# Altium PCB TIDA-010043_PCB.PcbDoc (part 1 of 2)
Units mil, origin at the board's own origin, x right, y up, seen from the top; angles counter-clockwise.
Board outline 2300 x 1555.91 mil, 4 copper layers (Top Layer, GND, PWR, Bottom Layer), stack 84.834 mil thick; 121 components, 65 nets, 295 pads, 120 vias.
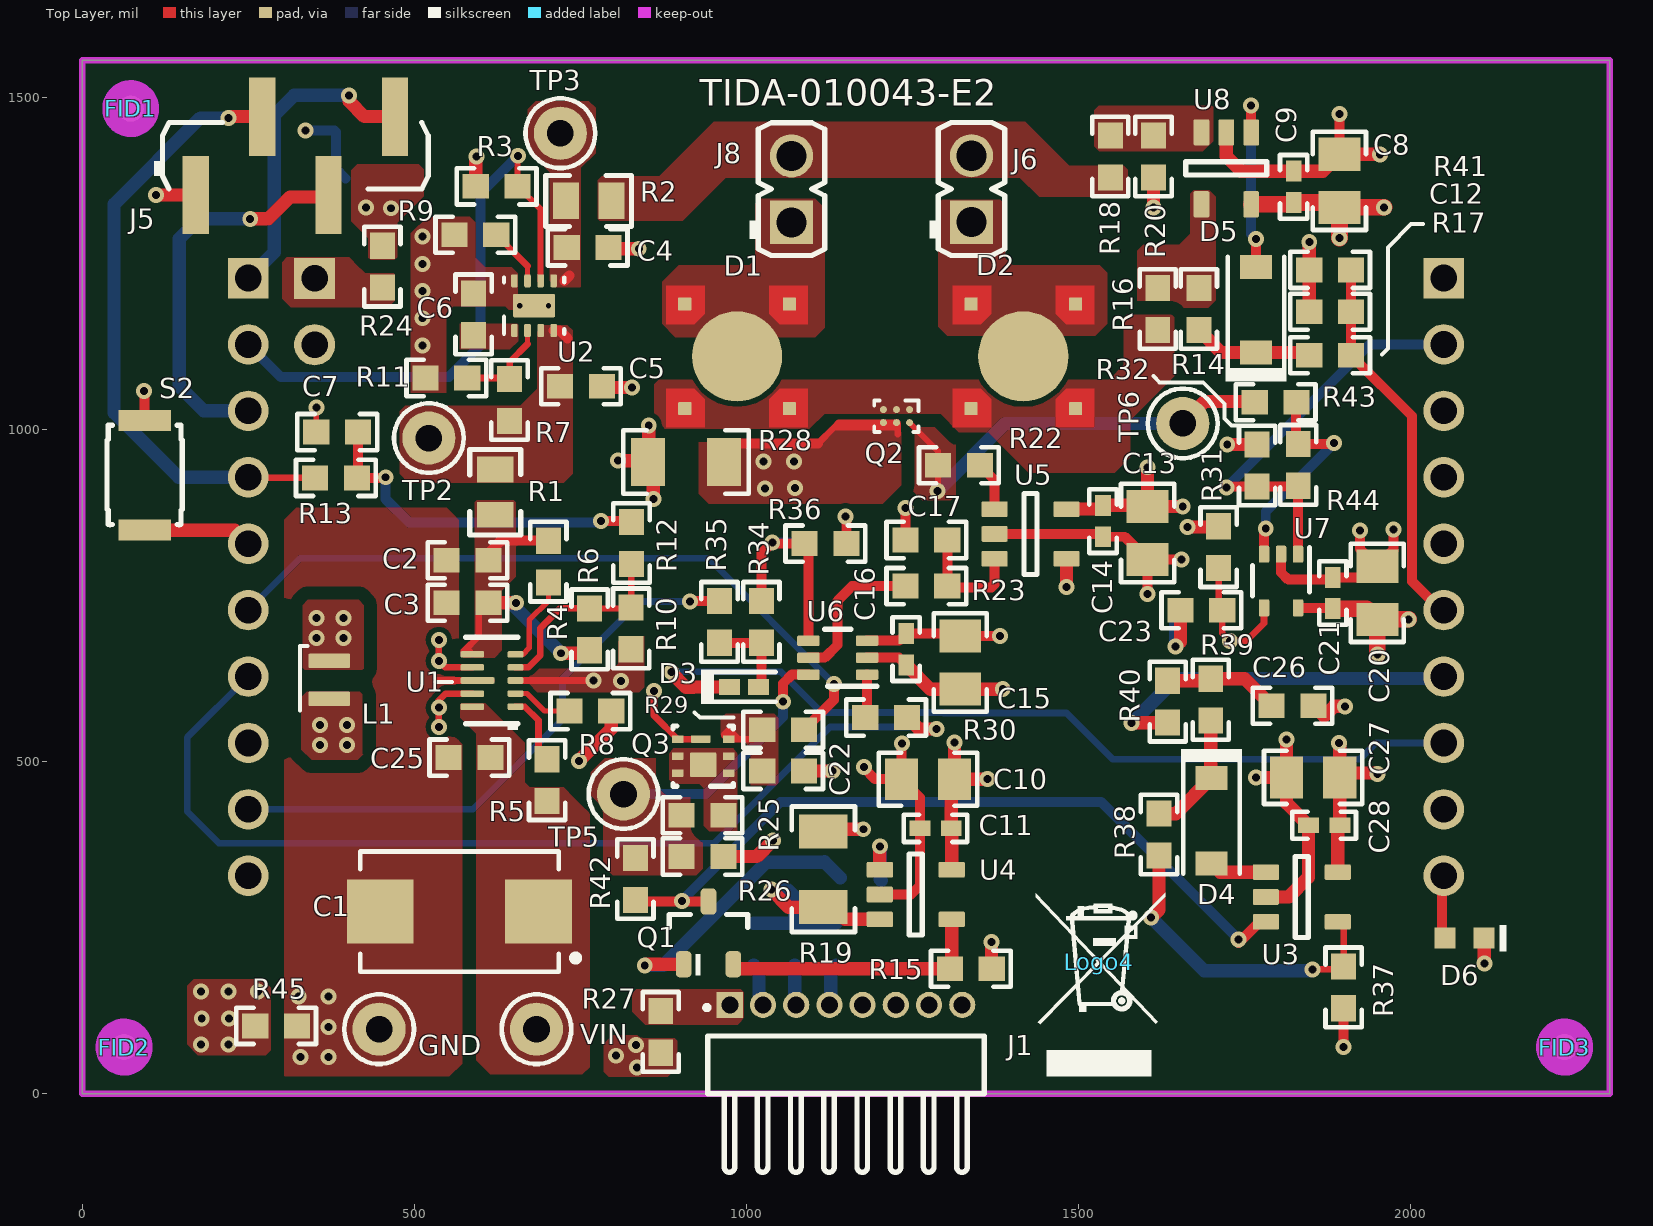
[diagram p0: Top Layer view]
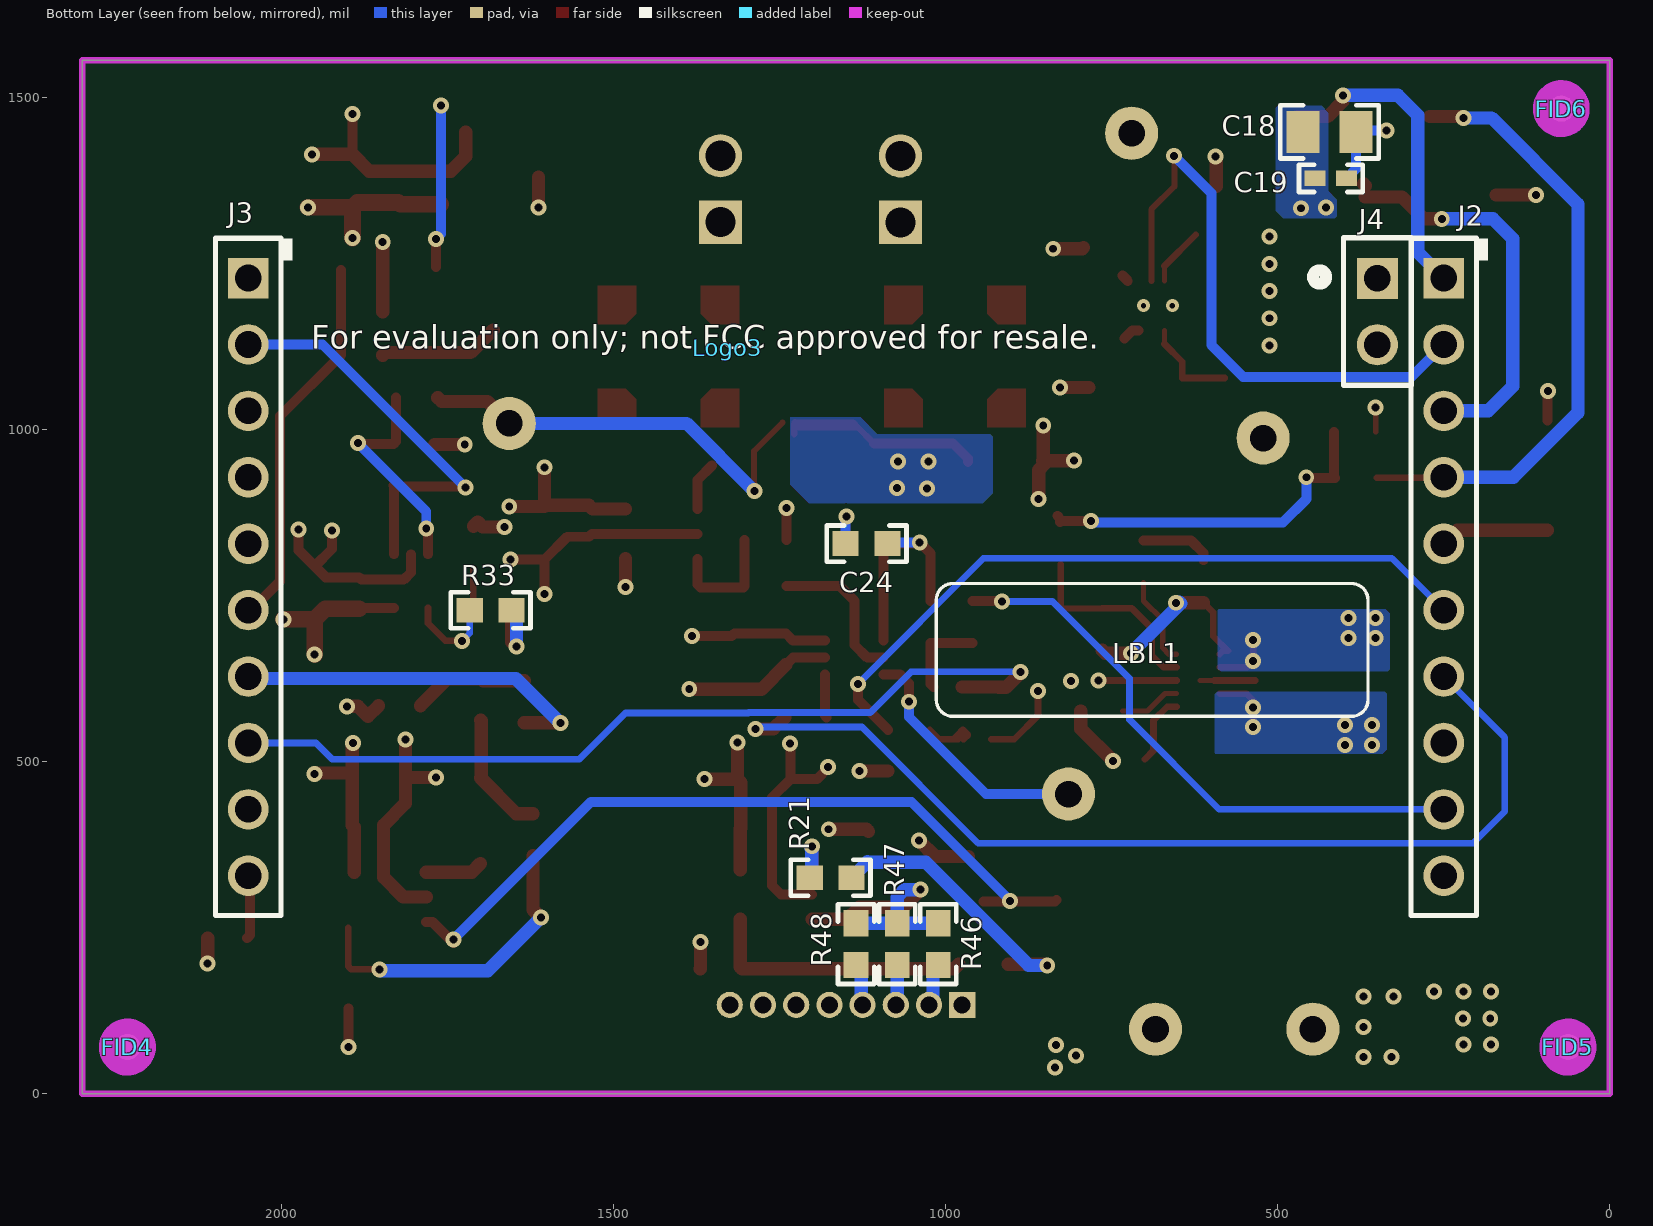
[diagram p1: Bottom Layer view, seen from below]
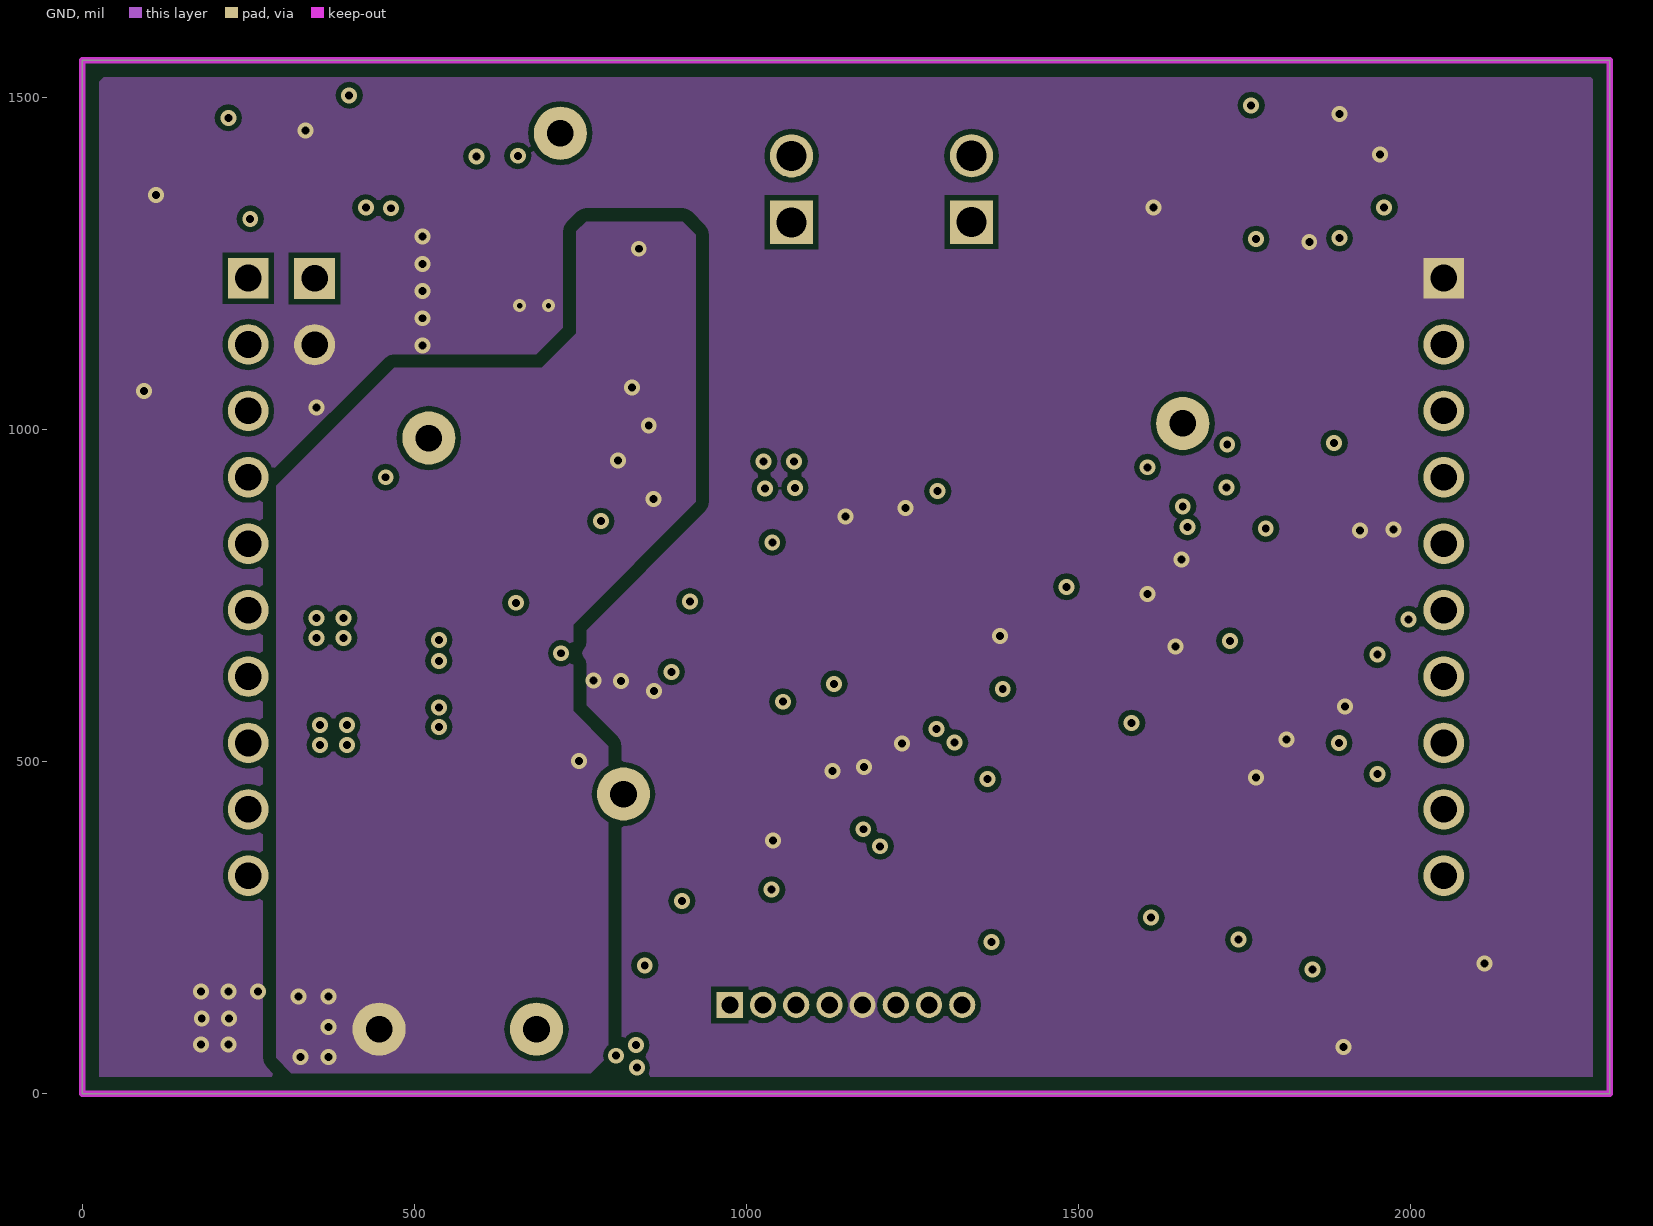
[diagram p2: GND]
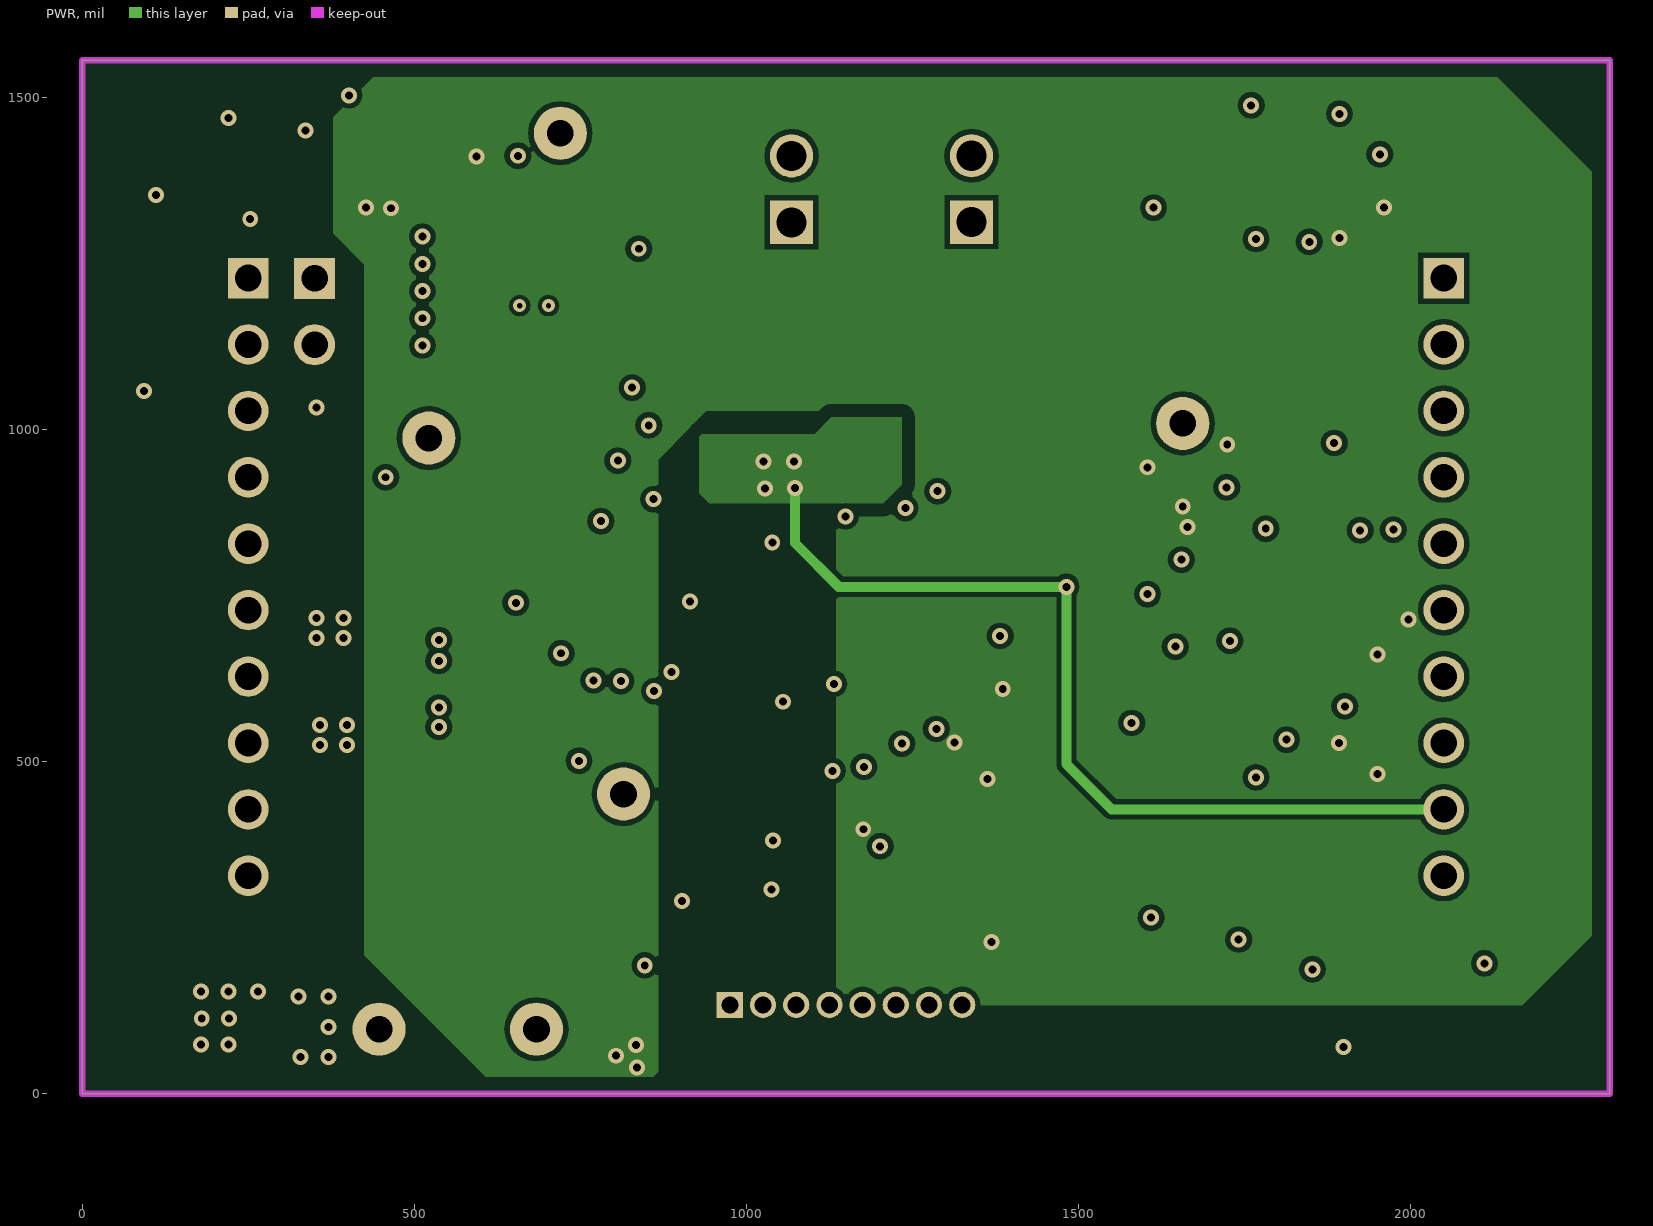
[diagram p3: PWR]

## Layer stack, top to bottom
Top Solder: solder mask 0.4, Solder Resist, Dk 3.5
Top Layer: signal copper 1.4
Dielectric 2: dielectric 10, FR-4 High Tg, Dk 4.2
GND: signal copper 1.417
Dielectric1: core 59.2, FR-4 High Tg, Dk 4.8
PWR: signal copper 1.417
Dielectric 3: dielectric 10, FR-4 High Tg, Dk 4.2
Bottom Layer: signal copper 1.4
Bottom Solder: solder mask 0.4, Solder Resist, Dk 3.5

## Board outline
0,0 2300,0 2300,1555.91 0,1555.91

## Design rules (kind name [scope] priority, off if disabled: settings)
AcuteAngle [All] p1: minimum=4.50000000000000E+0001 checktracksonly=FALSE
AssemblyTestPointUsage [All] p1: valid=2
BoardOutlineClearance BoardOutlineClearance_MountingHoles [OnCopper and InComponentClass('Mounting Holes')] p1: gap=0 ignorepadtopadclearanceinfootprint=FALSE
BoardOutlineClearance BoardOutlineClearance_Poly [OnCopper and IsPoly] p2: gap=0 ignorepadtopadclearanceinfootprint=FALSE
BoardOutlineClearance [OnCopper and Not InComponentClass('Logo') and not InComponentClass('FiducialMark') and not InRegion(1000,500,4000,800) and not InPoly] p3: gap=20 ignorepadtopadclearanceinfootprint=FALSE
Clearance "KEEPOU TO POLY" [IsKeepOut vs InPolygon] p1: gap=20 ignorepadtopadclearanceinfootprint=FALSE except(0: Arc-Hole Track-Hole SMDPad-Hole THPad-Hole Via-Hole Fill-Hole Poly-Hole Region-Hole Text-Hole)
Clearance U2 [InComponent('U2')] p2: gap=6 ignorepadtopadclearanceinfootprint=FALSE except(0: Arc-SMDPad Arc-Hole Track-Hole SMDPad-Hole THPad-Hole Via-Hole Fill-Hole Poly-Hole Region-Hole Text-Hole)
Clearance U1 [InComponent('U1')] p3: gap=6 ignorepadtopadclearanceinfootprint=FALSE except(0: Arc-SMDPad Arc-Hole Track-Hole SMDPad-Hole THPad-Hole Via-Hole Fill-Hole Poly-Hole Region-Hole Text-Hole)
Clearance Clearance_Poly [InPolygon vs InPolygon] p4: gap=20 ignorepadtopadclearanceinfootprint=FALSE except(0: Arc-SMDPad Arc-Hole Track-Hole SMDPad-Hole THPad-Hole Via-Hole Fill-Hole Poly-Hole Region-Hole Text-Hole)
Clearance [All] p5: gap=7.87 ignorepadtopadclearanceinfootprint=FALSE except(0: Arc-SMDPad Arc-Hole Track-Hole SMDPad-Hole THPad-Hole Via-Hole Fill-Hole Poly-Hole Region-Hole Text-Hole; 6: Arc-Arc Arc-Track Track-Track; 6.69: Track-SMDPad)
ComponentClearance ComponentClearance_MountingHoles_FiducialMarks [InComponentClass('Mounting Holes') vs InComponentClass('FiducialMark')] p1: gap=10 collisioncheckmode=3 verticalgap=10 showdistances=FALSE
ComponentClearance ComponentClearance_Shunt [InComponentClass('Header') vs InComponentClass('Shunt')] p2: gap=0 collisioncheckmode=3 verticalgap=0 showdistances=FALSE
ComponentClearance ComponentClearance_Logo [InComponentClass('Logo')] p3: gap=0 collisioncheckmode=3 verticalgap=0 showdistances=FALSE
ComponentClearance ComponentClearance_ScrewToNut [(HasFootprint('NY PMS 440 0025 PH')) vs (HasFootprint('Keystone_1902C'))] p4: gap=5 collisioncheckmode=3 verticalgap=10 showdistances=FALSE
ComponentClearance ComponentClearance_MountingHoles [InComponentClass('Mounting Holes')] p5: gap=10 collisioncheckmode=3 verticalgap=100000 showdistances=FALSE
ComponentClearance ComponentClearance_SmallPassives [HasFootprint('0201*') or HasFootprint('0402*') or HasFootprint('0508') or HasFootprint('0603*') or HasFootprint('0612') or HasFootprint('0805*') or HasFootprint('0815*') or HasFootprint('0830*') or HasFootprint('1206*') or HasFootprint('1210*') or HasFootprint('1808*') or HasFootprint('1812*') or HasFootprint('1825*') or HasFootprint('2010*') or HasFootprint('2220*') or HasFootprint('2225*') or HasFootprint('2512*') or HasFootprint('2728*') or HasFootprint('3518*') vs HasFootprint('0201*') or HasFootprint('0402*') or HasFootprint('0508') or HasFootprint('0603*') or HasFootprint('0612') or HasFootprint('0805*') or HasFootprint('0815*') or HasFootprint('0830*') or HasFootprint('1206*') or HasFootprint('1210*') or HasFootprint('1808*') or HasFootprint('1812*') or HasFootprint('1825*') or HasFootprint('2010*') or HasFootprint('2220*') or HasFootprint('2225*') or HasFootprint('2512*') or HasFootprint('2728*') or HasFootprint('3518*')] p6: gap=14.96 collisioncheckmode=3 verticalgap=10 showdistances=FALSE
ComponentClearance ComponentClearance_THtoSMT [IsThruComponent vs IsSMTComponent] p7: gap=0 collisioncheckmode=3 verticalgap=0 showdistances=FALSE
ComponentClearance ComponentClearance_THtoTH [IsThruComponent vs IsThruComponent] p8: gap=0 collisioncheckmode=3 verticalgap=0 showdistances=FALSE
ComponentClearance [All] p9: gap=0 collisioncheckmode=3 verticalgap=0 showdistances=FALSE
DiffPairsRouting [All] p1: maxlimit=100 minlimit=10 mostfreqgap=10 toplayer_minwidth=15 toplayer_maxwidth=15 toplayer_prefwidth=15 midlayer1_minwidth=15 midlayer1_maxwidth=15 midlayer1_prefwidth=15 midlayer2_minwidth=15 midlayer2_maxwidth=15 midlayer2_prefwidth=15 bottomlayer_minwidth=15 bottomlayer_maxwidth=15 bottomlayer_prefwidth=15 maxuncoupledlength=1000
FabricationTestPointUsage TestPointUsage [All] p1: valid=2 allowmultiple=FALSE
FabricationTestpoint Testpoint [All] p1: side=3 testpointundercomponent=TRUE minsize=40 maxsize=100 preferedsize=60 minholesize=0 maxholesize=40 preferedholesize=32 testpointgrid=1 allowsidetop=TRUE allowsidebottom=TRUE usegrid=TRUE gridtolerance=0.01
FanoutControl Fanout_LCC [IsLCC] p1: bgadir=Out bgaviamode=Centered fanoutstyle=Auto fanoutdirection=Alternating viagrid=1 // Fanout_LCC (Default Rule)
FanoutControl Fanout_BGA [IsBGA] p2: bgadir=Out bgaviamode=Centered fanoutstyle=Auto fanoutdirection=Alternating viagrid=1 // Fanout_BGA (Default Rule)
FanoutControl Fanout_Default [All] p4: bgadir=Out bgaviamode=Centered fanoutstyle=Auto fanoutdirection=Alternating viagrid=1 // Fanout_Default (Default Rule)
FanoutControl Fanout_Small [(CompPinCount < 5)] p5: bgadir=Out bgaviamode=Centered fanoutstyle=Auto fanoutdirection=OutThenIn viagrid=1 // Fanout_Small (Default Rule)
HoleSize [All] p1: absolutevalues=TRUE maxlimit=251 minlimit=7.87 maxpercent=80.000 minpercent=20.000
MinimumAnnularRing MinimumAnnularRing_ThermalPadVias [IsVia and InAnyComponent] p1: minimumring=5.91
MinimumAnnularRing [All] p2: minimumring=6
MinimumSolderMaskSliver MinimumSolderMaskSliver_Logo [InComponentClass('Logo') vs InComponentClass('Logo')] p1: minsoldermaskwidth=0.7
MinimumSolderMaskSliver [All] p2: minsoldermaskwidth=3.94
PlaneConnect [All] p1: planeconnectstyle=Direct reliefexpansion=10 reliefentries=4 reliefconductorwidth=10 reliefairgap=10
PolygonConnect [All] p1: connectstyle=Direct reliefconductorwidth=10 reliefentries=4 polygonreliefangle="90 Angle" airgapwidth=10
RoutingVias ThermalPadVias [IsVia and InAnyComponent] p1: holewidth=7.87 width=19.68 viastyle="Through Hole" minholewidth=7.87 minwidth=19.68 maxholewidth=12.99 maxwidth=23.62
RoutingVias [All] p2: holewidth=12 width=24 viastyle="Through Hole" minholewidth=12 minwidth=24 maxholewidth=12 maxwidth=24
SilkToBoardRegionClearance [Not ((IsComment or IsDesignator) And (Hide <> 'False')) and not InRegion(1000,500,4000,800)] p1:
SilkToSilkClearance SilkToSilkClearance_Pb-FreeLogo [(HasFootprint('Pb-Free_Overlay_Medium') OR HasFootprint('Pb-Free_Overlay_Small')) vs (HasFootprint('Pb-Free_Overlay_Medium') OR HasFootprint('Pb-Free_Overlay_Small'))] p1: silktosilkclearance=0
SilkToSilkClearance [All] p2: silktosilkclearance=4
SilkToSolderMaskClearance SilkToComponentPadClearance [(IsPad or IsFill or IsRegion) and InAnycomponent] p1: minsilkscreentomaskgap=5 clearancetoexposedcopper=TRUE
SilkToSolderMaskClearance "Silk to Solder Mask Opening" [All] p2: minsilkscreentomaskgap=4 clearancetoexposedcopper=FALSE
SolderMaskExpansion [All] p1: expansion=1.97
Width [All] p1: maxlimit=100 minlimit=8 preferedwidth=15 checkconnectedcopper=TRUE
15 further rules are at their usual default settings.

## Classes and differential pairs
component class TIDA-010043_Main: C1 C2 C3 C4 C5 C6 C7 C8 C9 C10 C11 C12 C13 C14 C15 C16 C17 C18 C19 C20 C21 C22 C23 C24 C25 C26 C27 C28 D1 D2 D3 D4 D5 D6 GND J1 J2 J3 J4 J5 J6 J8 L1 Q1 Q2 Q3 R1 R2 R3 R4 R5 R6 R7 R8 R9 R10 R11 R12 R13 R14 R15 R16 R17 R18 R19 R20 R21 R22 R23 R24 R25 R26 R27 R28 R29 R30 R31 R32 R33 R34 R35 R36 R37 R38 R39 R40 R41 R42 R43 R44 R45 R46 R47 R48 S2 TP2 TP3 TP5 TP6 U1 U2 U3 U4 U5 U6 U7 U8 VIN
component class TIDA-010043_EVM_Hardware: FID1 FID2 FID3 FID4 FID5 FID6 LBL1 Logo3 Logo4 ZZ1 ZZ2 ZZ3 ZZ4
component class FiducialMark: FID1 FID2 FID3 FID4 FID5 FID6
component class AssemblyNote: ZZ1 ZZ2 ZZ3 ZZ4
component class Label: LBL1
component class Header: J5 J6 J8

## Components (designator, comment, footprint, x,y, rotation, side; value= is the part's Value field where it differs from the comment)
C1 "T495D686K020ATE150" 7343-31 568,274 r180 top value=68uF
C2 "GRM188R60J226MEA0D" 0603 580.13,803 r180 top value=22uF
C3 "GRM188R60J226MEA0D" 0603 580.13,739 r180 top value=22uF
C4 "GRM188Z71A106MA73D" 0603 761,1274 r0 top value=10uF
C5 "06033C104KAT2A" 0603 751,1065 r0 top value=0.1uF
C6 "GRM188R71E332KA01D" 0603 589.32,1173.37 r90 top value=3300pF
C7 "06033C104KAT2A" 0603 384,996 r180 top value=0.1uF
C8 "885012207026" 0805_HV 1893,1374.22 r90 top value=10uF
C9 "885012205037" 0402 1824,1365.22 r90 top value=0.1uF
C10 "885012207026" 0805_HV 1273.43,473.37 r180 top value=10uF
C11 "885012205037" 0402 1284.81,399.37 r180 top value=0.1uF
C12 "06033C104KAT2A" 0603 1879,1177.22 r180 top value=0.1uF
C13 "885012207026" 0805_HV 1604,844 r270 top value=10uF
C14 "885012205037" 0402 1537,862 r270 top value=0.1uF
C15 "885012207026" 0805_HV 1322,649 r90 top value=10uF
C16 "885012205037" 0402 1240.56,669.21 r90 top value=0.1uF
C17 "06033C104KAT2A" 0603 1271,833.53 r180 top value=0.1uF
C18 "885012207026" 0805_HV 422,1448 r180 bottom value=10uF
C19 "885012205037" 0402 420,1378 r180 bottom value=0.1uF
C20 "885012207026" 0805_HV 1950,754 r90 top value=10uF
C21 "885012205037" 0402 1883,753.71 r90 top value=0.1uF
C22 "06033C104KAT2A" 0603 1055.35,485.7 r0 top value=0.1uF
C23 "06033C104KAT2A" 0603 1685,727.71 r180 top value=0.1uF
C24 "06033C104KAT2A" 0603 1119,828.21 r0 bottom value=0.1uF
C25 "GRM188R60J106ME84" 0603 583,506 r180 top value=10uF
C26 "GRM188R71A474KA61D" 0603 1822.29,584 r0 top value=0.47uF
C27 "885012207026" 0805_HV 1853.29,476 r180 top value=10uF
C28 "885012205037" 0402 1869.91,404 r180 top value=0.1uF
D1 "LZ1-00G102-0000" LED_LZ1_Green 986,1110 r270 top value=Green
D2 "LZ1-00R102-0000" LED_LZ1_Red 1417,1109.92 r90 top value=Red
D3 "ZLLS350TA" SOD-523 996.56,612.21 r0 top value=40V
D4 "1N4148W-7-F" SOD-123 1700.29,411 r270 top value=100V
D5 "1N4148W-7-F" SOD-123 1767.32,1180.22 r90 top value=100V
D6 "SM0603GCL" SM0603GCL_GREEN 2081.29,234 r0 top value=Green
FID1 "Fiducial" Fiducial10-20 73,1483 r0 top
FID2 "Fiducial" Fiducial10-20 63,70 r0 top
FID3 "Fiducial" Fiducial10-20 2232,70 r0 top
FID4 "Fiducial" Fiducial10-20 2232,70 r180 bottom
FID5 "Fiducial" Fiducial10-20 63,70 r180 bottom
FID6 "Fiducial" Fiducial10-20 73,1483 r180 bottom
GND "5001" Keystone5001 447,97 r90 top
J1 "850-10-008-20-001000" Mill-Max_850-10-008-20-001000 1150,0 r0 top
J2 "61301011821" Wurth_61301011821 250,777.95 r270 bottom
J3 "61301011821" Wurth_61301011821 2050,777.95 r270 bottom
J4 "PPTC021LFBN-RC" CONN_PPTC021LFBN-RC 350,1177.46 r90 bottom
J5 "61000418221" Wurth_61000418221 321,1412 r90 top
J6 "61300211121" WURTH_61300211121 1339,1362 r90 top
J8 "61300211121" WURTH_61300211121 1068,1361.86 r90 top
L1 "DFE201612E-R47M=P2" DFE201612E 372,623 r90 top value=470nH
LBL1 "Size: 0.65\" x 0.20 \"" Label_650x200 689,668 r180 bottom
Logo3 "FCC disclaimer" FCC_disclaimer 1328,1123 r180 bottom
Logo4 "WEEE logo" WEEE_Minimum 1531,198 r0 top
Q1 "BC857C-7-F" SOT-23 943,242 r90 top value="45 V"
Q2 "CSD13306W" YZC0006ABAB 1226,1020 r270 top value=12V
Q3 "CSD13202Q2" DQK0006C 935,508 r180 top value=12V
R1 "5106" 5106 622,905 r90 top value=0
R2 "5106" 5106 762,1344 r0 top value=0
R3 "RC0603FR-0710K2L" 0603 624,1366 r180 top value=10.2k
R4 "RC0603FR-07806KL" 0603 764,699 r270 top value=806k
R5 "RMCF0603ZT0R00" 0603 700,472 r90 top value=0
R6 "CRCW0603100KFKEA" 0603 702,800.94 r270 top value=100k
R7 "RC0603FR-071ML" 0603 643.32,1044.37 r270 top value=1.00Meg
R8 "RMCF0603ZT0R00" 0603 765,576 r180 top value=0
R9 "RC0603FR-071K4L" 0603 592,1293 r0 top value=1.40k
R10 "CRCW0603100KFKEA" 0603 826.5,700.45 r270 top value=100k
R11 "RC0603FR-07390KL" 0603 548.32,1077.37 r0 top value=390k
R12 "RC0603FR-07806KL" 0603 827,829 r270 top value=806k
R13 "RMCF0603ZT0R00" 0603 382,927 r180 top value=0
R14 "RMCF0603FT10K0" 0603 1681.32,1181.22 r270 top value=10.0k
R15 "ERJ-3EKF1001V" 0603 1338,188 r0 top value=1.00k
R16 "RMCF0603FT10K0" 0603 1619.32,1181.22 r90 top value=10.0k
R17 "RMCF0603ZT0R00" 0603 1879,1111.68 r0 top value=0
R18 "RMCF0603FT10K0" 0603 1548,1411 r90 top value=10.0k
R19 "CRCW120620R0FKEAHP" 1206 1116,337.68 r90 top value=20.0
R20 "RMCF0603FT10K0" 0603 1613,1411 r90 top value=10.0k
R21 "RMCF0603ZT0R00" 0603 1173,325.05 r180 bottom value=0
R22 "RMCF0603ZT0R00" 0603 1320,946 r180 top value=0
R23 "RMCF0603ZT0R00" 0603 1271,764 r0 top value=0
R24 "RMCF0603ZT0R00" 0603 452,1245 r90 top value=0
R25 "CRCW06032R49FKEA" 0603 934,419 r180 top value=2.49
R26 "CRCW060349R9FKEA" 0603 934,357 r180 top value=49.9
R27 "RMCF0603ZT0R00" 0603 871,93 r270 top value=0
R28 "CRM1206-FZ-R050ELF" 1206 909,951 r0 top value=0.05
R29 "RMCF0603ZT0R00" 0603 1055.35,547.7 r180 top value=0
R30 "RMCF0603ZT0R00" 0603 1210.56,566.21 r180 top value=0
R31 "RC0603FR-0710K2L" 0603 1711,822.71 r90 top value=10.2k
R32 "RC0603FR-0710K2L" 0603 1769,945.71 r90 top value=10.2k
R33 "RC0603FR-0710K2L" 0603 1685,727.71 r0 bottom value=10.2k
R34 "RMCF0603ZT0R00" 0603 1022.56,710.21 r270 top value=0
R35 "RMCF0603ZT0R00" 0603 959.56,710.21 r90 top value=0
R36 "RMCF0603ZT0R00" 0603 1119,828.21 r180 top value=0
R37 "RC0603FR-071ML" 0603 1899.29,160 r90 top value=1.00Meg
R38 "RC0603FR-072ML" 0603 1621.29,390 r90 top value=2.00Meg
R39 "RMCF0603ZT0R00" 0603 1699.29,593 r90 top value=0
R40 "RMCF0603ZT0R00" 0603 1634.29,590 r270 top value=0
R41 "RC0603FR-07100KL" 0603 1879,1240.22 r0 top value=100k
R42 "ERJ-3EKF1001V" 0603 833,323 r270 top value=1.00k
R43 "ERJ-3EKF2202V" 0603 1797,1041 r0 top value=22.0k
R44 "RC0603FR-07470KL" 0603 1831,946.71 r270 top value=470k
R45 "RMCF0603ZT0R00" 0603 292,102 r180 top value=0
R46 "RMCF0603ZT0R00" 0603 1011,225 r90 bottom value=0
R47 "RMCF0603ZT0R00" 0603 1072.94,225 r90 bottom value=0
R48 "RMCF0603ZT0R00" 0603 1134.87,225 r90 bottom value=0
S2 "SKRKAEE010" SW_SKRKAEE010 94,931 r90 top
TP2 "5000" Keystone5000 521.98,987 r90 top
TP3 "5000" Keystone5000 720,1446 r90 top
TP5 "5000" Keystone5000 815,451 r0 top
TP6 "5000" Keystone5000 1657,1009 r90 top
U1 "TPS63802DLAR" DLA0010A 616.92,621.95 r180 top
U2 "TPS259571DSGR" DSG0008A 680.32,1186.37 r90 top
U3 "OPA333AIDBVR" DBV0005A_N 1836.29,296 r0 top
U4 "OPA365AIDBVR" DBV0005A_N 1255,299.68 r0 top
U5 "OPA365AIDBVR" DBV0005A_N 1427.84,842.62 r0 top
U6 "TS5A9411DCKR" DCK0006A_N 1137.56,656.26 r180 top
U7 "TLV7021DCKR" DCK0005A_L 1805,771.71 r270 top
U8 "OPA333AIDBVR" DBV0005A_N 1722.6,1393.08 r270 top
VIN "5000" Keystone5000 684,97 r90 top
ZZ1 "This Assembly Note is for PCB labels only" AssemblyNoteLabel 181.5,3681.95 r0 top
ZZ2 "These assemblies are ESD sensitive, ESD precautions shall be observed." AssemblyNote 185,3607.07 r0 top
ZZ3 "These assemblies must be clean and free from flux and all contaminants. Use of no clean flux is not acceptable." AssemblyNote 185,3518.51 r0 top
ZZ4 "These assemblies must comply with workmanship standards IPC-A-610 Class 2, unless otherwise specified." AssemblyNote 185,3429.95 r0 top

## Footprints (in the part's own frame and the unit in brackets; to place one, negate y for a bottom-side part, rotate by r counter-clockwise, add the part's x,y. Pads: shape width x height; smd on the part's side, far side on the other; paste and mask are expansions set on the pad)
0402 [mm] "0402 from SM-752 data"
  rect 0.8x0.6 smd: 1(-0.6,0) 2(0.6,0)
  silkscreen extent -1.22,-0.52 1.22,0.52, body extent -0.55,-0.3 0.55,0.3, height 0.6
0603 [mm] "0603 from SM-752 data"
  rect 1x0.95 smd: 1(-0.8,0) 2(0.8,0)
  silkscreen extent -1.52,-0.69 1.52,0.69, body extent -0.87,-0.47 0.87,0.47, height 1
0805_HV [mil] "0805 with 30mil clearance between pads"
  rect 50x63 smd: 1(-40,0) 2(40,0)
  silkscreen extent -74,-40 74,40, body extent -43,-29 43,29, height 57
1206 [mm] "1206 from SM-752 data"
  rect 1.3x1.85 smd: 1(-1.45,0) 2(1.45,0)
  silkscreen extent -2.4,-1.21 2.4,1.21, body extent -1.7,-0.9 1.7,0.9, height 1.35
5106 [mm] "Keystone"
  rect 0.99x1.4 smd: 1(-0.85,0) 2(0.88,0)
  silkscreen extent -1.63,-0.97 1.65,0.97, body extent -1.06,-0.69 1.06,0.69, height 0.84
7343-31 [mm] "Medium Density based on Kemet T495 dimensions"
  rect 2.55x2.45 smd: 1(-3.025,0) 2(3.025,0)
  silkscreen extent -4.56,-2.3 3.8,2.3, body extent -3.8,-2.3 3.8,2.3, height 3.1
AssemblyNote [mil] "Assembly Note"
AssemblyNoteLabel [mil] "Assembly Note for PCB Labels"
CONN_PPTC021LFBN-RC [mil] "SULLINS"
  rect 62x62 hole 40: 1(50,0)
  round 62 hole 40.16: 2(-50,0)
  silkscreen extent -111,-51 111,97, body extent -110,-50 110,50, height 336
DBV0005A_N [mm] "SOT23, 5-Leads, Body 2.9x1.6mm, Pitch 0.95mm, Lead Span 2.8mm, IPC Medium Density"
  rrect17% 1x0.6 smd: 1(-1.375,0.95) 2(-1.375,0) 3(-1.375,-0.95) 4(1.375,-0.95) 5(1.375,0.95)
  silkscreen extent -0.25,-1.55 0.25,1.55, body extent -1.42,-1.46 1.42,1.46, height 1.09
DCK0005A_L [mm] "SOT353, 5-Leads, Body 2x1.3mm, Pitch 0.65mm, Lead Span 2.1mm, IPC High Density"
  rrect25% 0.65x0.4 smd: 1(-1.025,0.65) 2(-1.025,0) 3(-1.025,-0.65) 4(1.025,-0.65) 5(1.025,0.65)
  silkscreen extent -1.27,-1.09 0.56,1.09, body extent -1.14,-1 1.14,1, height 0.95
DCK0006A_N [mm] "SOT23, 6-Leads, Body 2x1.3mm, Pitch 0.65mm, Lead Span 2.1mm, IPC Medium Density"
  rrect25% 0.85x0.4 smd: 1(-1.125,0.65) 2(-1.125,0) 3(-1.125,-0.65) 4(1.125,-0.65) 5(1.125,0) 6(1.125,0.65)
  silkscreen extent -1.5,-1.09 0.51,1.09, body extent -1.14,-1 1.14,1, height 0.95
DFE201612E [mm] "MuRata recommended"
  rrect18% 0.55x1.6 smd: 1(-0.725,0) 2(0.725,0)
  body extent -1.1,-0.9 1.1,0.9, height 1.2
DLA0010A [mm] "VQFN-HR-10"
  rrect40% 0.6x0.25 smd: 1(-0.9,1) 2(-0.9,0.5) 3(-0.9,0) 4(-0.9,-0.5) 5(-0.9,-1)
  rrect40% 0.9x0.25 smd: 6(0.75,-1) 7(0.75,-0.5) 9(0.75,0.5) 10(0.75,1)
  rrect40% 1.3x0.25 smd paste-1: 8(0.55,0)
  silkscreen extent -1,-1.65 1,1.9, body extent -1,-1.5 1,1.5, height 1
DQK0006C [mm] "WSON"
  rrect12% 0.9x0.86 on Top Paste: 0(0,0.325)
  rrect34% 0.7x0.29 on Top Paste: 0(0.095,-0.65)
  rrect33% 0.45x0.3 smd: 1(-0.975,0.65) 2(-0.975,0) 3(-0.975,-0.65) 4(0.975,-0.65) 5(0.975,0) 6(0.975,0.65)
  rrect33% 0.75x0.3 smd paste-0.15: 7(0.095,-0.65)
  rrect11% 1x0.95 smd paste-0.5: 8(0,0.325)
  silkscreen extent -1.15,-1.15 1.15,1.15, body extent -1,-1 1,1, height 0.82
DSG0008A [mm] "SON, 8-Leads, Body 2x2mm, Pitch 0.5mm, Thermal Pad 1.6x0.9mm, TI Recommended"
  rrect40% 0.5x0.25 smd: 1(-0.95,0.75) 2(-0.95,0.25) 3(-0.95,-0.25) 4(-0.95,-0.75) 5(0.95,-0.75) 6(0.95,-0.25) 7(0.95,0.25) 8(0.95,0.75)
  rrect14% 0.9x0.7 on Top Paste: 9(0,0.45) 9(0,-0.45)
  rrect11% 0.9x1.6 smd paste-0.45: 9(0,0)
  silkscreen extent -1.07,-1.15 1.07,1.15, body extent -1,-1 1,1, height 0.77
FCC_disclaimer [mil]
Fiducial10-20 [mm]
  round 1 smd mask+0.5: 1(0,0)
  Top Layer keep-out circle w1.178: c0,0 r0.5
Keystone5000 [mil] "For Keystone 500x miniature loop terminals"
  round 80 hole 40: 1(0,0)
  silkscreen extent -52,-52 52,52, body extent -49,-49 49,49, height 182
Keystone5001 [mil] "For Keystone 500x miniature loop terminals"
  round 80 hole 40: 1(0,0)
  silkscreen extent -52,-52 52,52, body extent -49,-49 49,49, height 182
Label_650x200 [mil] "Thermal Transfer Label"
  silkscreen extent -325,-100 325,100, body extent -325,-100 325,100, height 1
LED_LZ1_Green [mm] "SMD, 5-Leads, Body 4.4x4.4m"
  rrect12% 0.5x0.5 smd: 1(-2,2) 2(2,2) 3(2,-2) 4(-2,-2)
  round 3.45 smd paste-0.125 mask-0.125: 5(0,0)
  Top Layer region: 2.706,2.704 2.706,1.234 1.636,1.234 1.236,1.634 1.236,2.704
  Top Layer region: 2.706,-2.706 1.236,-2.706 1.236,-1.636 1.636,-1.236 2.706,-1.236
  Top Layer region: -2.704,2.704 -1.234,2.704 -1.234,1.634 -1.634,1.234 -2.704,1.234
  Top Layer region: -2.704,-2.706 -2.704,-1.236 -1.634,-1.236 -1.234,-1.636 -1.234,-2.706
  body extent -2.2,-2.2 2.2,2.2, height 2.35
LED_LZ1_Red [mm] "SMD, 5-Leads, Body 4.4x4.4m"
  rrect12% 0.5x0.5 smd: 1(-2,2) 2(2,2) 3(2,-2) 4(-2,-2)
  round 3.45 smd paste-0.125 mask-0.125: 5(0,0)
  Top Layer region: 2.706,2.704 2.706,1.234 1.636,1.234 1.236,1.634 1.236,2.704
  Top Layer region: 2.706,-2.706 1.236,-2.706 1.236,-1.636 1.636,-1.236 2.706,-1.236
  Top Layer region: -2.704,2.704 -1.234,2.704 -1.234,1.634 -1.634,1.234 -2.704,1.234
  Top Layer region: -2.704,-2.706 -2.704,-1.236 -1.634,-1.236 -1.234,-1.636 -1.234,-2.706
  body extent -2.2,-2.2 2.2,2.2, height 2.35
Mill-Max_850-10-008-20-001000 [mm] "Mill-Max"
  rect 1x1 hole 0.65: 1(-4.445,3.394)
  round 1 hole 0.65: 2(-3.175,3.394) 3(-1.905,3.394) 4(-0.635,3.394) 5(0.635,3.394) 6(1.905,3.394) 7(3.175,3.394) 8(4.445,3.394)
  silkscreen extent -5.37,-3.01 5.28,3.34, body extent -5.27,-3 5.27,3.6, height 2.21
SM0603GCL_GREEN [mm] "BIVAR"
  rect 0.8x0.8 smd: 1(-0.75,0) 2(0.75,0)
  silkscreen extent 1.35,-0.51 1.6,0.51, body extent -0.93,-0.52 0.93,0.52, height 0.86
SOD-123 [mm] "On Semi recommended land pattern"
  rect 0.915x1.22 smd: 1(-1.637,0) 2(1.637,0)
  silkscreen extent -2.74,-1.17 2.03,1.17, body extent -1.93,-0.9 1.93,0.9, height 1.35
SOD-523 [mm] "NXP Semiconductor recommended land pattern, nominal STEP model"
  rect 0.8x0.6 smd paste-0.05: 1(-0.55,0) 2(0.55,0)
  silkscreen extent -1.65,-0.66 1.2,0.66, body extent -0.8,-0.4 0.8,0.4, height 0.72
SOT-23 [mm] "SOT23, 3-Leads, Body 2.9x1.3mm, Pitch 0.95mm, Lead Span 2.5mm, IPC Medium Density"
  rrect50% 1x0.6 smd: 1(-1.2,0.95) 2(-1.2,-0.95) 3(1.2,0)
  silkscreen extent -1.62,-1.5 0.7,1.5, body extent -1.16,-1.45 1.21,1.45, height 1
SW_SKRKAEE010 [mm] "Alps recommended land pattern"
  rect 0.8x2 smd: 1(-2.1,0) 2(2.1,0)
  silkscreen extent -1.9,-1.44 1.92,1.44, body extent -2.4,-1.45 2.4,1.45, height 1.96
WEEE_Minimum [mil] "WEEElie bin"
  silkscreen extent -95,-172 99,104
Wurth_61000418221 [mm] "Header, 2.54mm, 4x1, SMT"
  rect 3x1 smd: 1(-1.5,3.81) 2(1.5,1.27) 3(-1.5,-1.27) 4(1.5,-3.81)
  silkscreen extent -1.27,-5.08 1.27,5.4, body extent -2.5,-5.08 2.5,5.08, height 9.29
WURTH_61300211121 [mm] "Header, 2.54mm, 2x1, TH"
  rect 1.65x1.65 hole 1.15: 1(-1.27,0)
  round 1.65 hole 1.15: 2(1.27,0)
  silkscreen extent -2.54,-1.27 2.54,1.6, body extent -2.54,-1.27 2.54,1.27, height 8.54
Wurth_61301011821 [mm] "Receptacle, 2.54mm, 10x1, TH"
  rect 1.55x1.55 hole 1.02: 1(-11.43,0)
  round 1.55 hole 1.02: 2(-8.89,0) 3(-6.35,0) 4(-3.81,0) 5(-1.27,0) 6(1.27,0) 7(3.81,0) 8(6.35,0) 9(8.89,0) 10(11.43,0)
  silkscreen extent -12.95,-1.25 12.95,1.7, body extent -12.95,-1.25 12.95,1.25, height 8.5
YZC0006ABAB [mm] "DSBGA"
  round 0.265 smd paste-0.125: A1(-0.25,0.5) A2(0.25,0.5) B1(-0.25,0) B2(0.25,0) C1(-0.25,-0.5) C2(0.25,-0.5)
  silkscreen extent -0.6,-0.85 0.6,0.85, body extent -0.5,-0.75 0.5,0.75, height 0.63

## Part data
C1: library part CMP-0011790-2, "CAP, TA, 68 uF, 20 V, +/- 10%, 0.15 ohm, SMD", Cap_Case=D, Manufacturer=Kemet, Supplier Part Number 1=399-3890-1-ND, Tolerance_%=10%, Value1="0.15 ohm", Value2=20V, ValueDisplayed=68uF
C2 C3: library part CMP-0007306-5, "CAP, CERM, 22 uF, 6.3 V, +/- 20%, X5R, 0603", Cap_Case=0603, Manufacturer=MuRata, Supplier Part Number 1=490-7611-1-ND, TempCo=X5R, Tolerance_%=20%, Value1=Unknown, Value2=6.3V, ValueDisplayed=22uF
C4: library part CMP-0007497-5, "CAP, CERM, 10 uF, 10 V, +/- 20%, X7R, 0603", Cap_Case=0603, Manufacturer=MuRata, Supplier Part Number 1=81-GRM188Z71A106MA3D, TempCo=X7R, Tolerance_%=20%, Value1=Unknown, Value2=10V, ValueDisplayed=10uF
C5 C7 C12 C17 C22 C23 C24: library part CMP-0006753-4, "CAP, CERM, 0.1 uF, 25 V, +/- 10%, X7R, 0603", Cap_Case=0603, Manufacturer=AVX, Supplier Part Number 1=478-3714-1-ND, TempCo=X7R, Tolerance_%=10%, Value1="0.05 ohm", Value2=25V, ValueDisplayed=0.1uF
C6: library part CMP-0007418-4, "CAP, CERM, 3300 pF, 25 V, +/- 10%, X7R, 0603", Cap_Case=0603, Manufacturer=MuRata, Supplier Part Number 1=GRM188R71E332KA01D-ND, TempCo=X7R, Tolerance_%=10%, Value1=Unknown, Value2=25V, ValueDisplayed=3300pF
C8 C10 C13 C15 C18 C20 C27: library part CMP-0007691-2, "CAP, CERM, 10 uF, 10 V, +/- 10%, X7R, 0805", Cap_Case=0805, Manufacturer="Wurth Elektronik", Supplier Part Number 1=710-885012207026, TempCo=X7R, Tolerance_%=10%, Value1=Unknown, Value2=10V, ValueDisplayed=10uF
C9 C11 C14 C16 C19 C21 C28: library part CMP-0006228-2, "CAP, CERM, 0.1 uF, 16 V, +/- 10%, X7R, 0402", Cap_Case=0402, Manufacturer="Wurth Elektronik", Supplier Part Number 1=732-7532-1-ND, TempCo=X7R, Tolerance_%=10%, Value1=Unknown, Value2=16V, ValueDisplayed=0.1uF
C25: library part CMP-0007304-5, "CAP, CERM, 10 uF, 6.3 V, +/- 20%, X5R, 0603", Cap_Case=0603, Manufacturer=MuRata, Supplier Part Number 1=490-7316-1-ND, TempCo=X5R, Tolerance_%=20%, Value1=Unknown, Value2=6.3V, ValueDisplayed=10uF
C26: library part CMP-0007373-4, "CAP, CERM, 0.47 uF, 10 V, +/- 10%, X7R, 0603", Cap_Case=0603, Manufacturer=MuRata, Supplier Part Number 1=GRM188R71A474KA61D-ND, TempCo=X7R, Tolerance_%=10%, Value1=Unknown, Value2=10V, ValueDisplayed=0.47uF
D1: library part CMP-0085613-1, "LED, Green, SMD", Color=Green, Manufacturer=LEDEngin, Value1=W, Value2=3.95V
D2: library part CMP-0085612-1, "LED, Red, SMD", Color=Red, Manufacturer=LEDEngin, Value1=W, Value2=3V
D3: library part CMP-0028378-3, "Diode, Schottky, 40 V, 0.38 A, SOD-523", Manufacturer="Diodes Inc.", Value1=0.38A, Value2=0.79V
D4 D5: library part CMP-0029001-2, "Diode, Ultrafast, 100 V, 0.15 A, SOD-123", Manufacturer="Diodes Inc.", Value1=0.15A, Value2=1.25V
D6: library part CMP-0002869-2, "LED, Green, SMD", Color=green, Manufacturer=Bivar, Value1=W, Value2=1.9V
FID1 FID2 FID3 FID4 FID5 FID6: "Fiducial mark.  There is nothing to buy or mount.", Manufacturer=N/A
GND: library part CMP-0055138-1, "Test Point, Miniature, Black, TH", Color=Black, Manufacturer=Keystone, Supplier Part Number 1=36-5001-ND
J1: library part CMP-0055014-1, "Header, 50mil, 8x1, R/A, TH", Manufacturer=Mill-Max
J2 J3: library part CMP-0054762-1, "Receptacle, 2.54mm, 10x1, Gold, TH", Color=Black, Current_A=3A, Manufacturer="Wurth Elektronik", Supplier Part Number 1=732-2859-ND, Voltage_V=250V
J4: library part CMP-0054631-1, "Receptacle, 100mil, 2x1, Tin, TH", Color=Black, Current_A=3A, Manufacturer="Sullins Connector Solutions", Supplier Part Number 1=S7000-ND, Voltage_V=250V
J5: library part CMP-0054788-1, "Header, 2.54mm, 4x1, Gold, SMT", Color=Black, Manufacturer="Wurth Elektronik", Supplier Part Number 1=732-5365-ND
J6 J8: library part CMP-0054794-1, "Header, 2.54 mm, 2x1, Gold, TH", Manufacturer="Wurth Elektronik", Supplier Part Number 1=732-5315-ND
L1: library part CMP-0080779-1, "Inductor, Shielded, Metal Composite, 470 nH, 4.5 A, 0.026 ohm, SMD", Manufacturer=MuRata, PartNumber=DFE201612E-R47M{}P2, Value1="0.026 ohm", Value2=4.5A, ValueDisplayed=470nH
LBL1: library part THT-14-423-10, "Thermal Transfer Printable Labels, 0.650\" W x 0.200\" H - 10,000 per roll", Alternate Manufacturer=-, Manufacturer=Brady, Supplier Part Number 1=2065596
Logo3: library part FCC_disclaimer, "FCC_disclaimer"
Logo4: library part CMP-0074769-1
Q1: library part CMP-0000316-2, "Transistor, PNP, 45 V, 0.1 A, SOT-23", Manufacturer="Diodes Inc.", Supplier Part Number 1=BC857C-FDICT-ND, Value1="0.1 A", Value2=600
Q2: library part CMP-0000196-1, "MOSFET, N-CH, 12 V, 3.5 A, YZC0006ABAB (DSBGA-6)", Alternate Manufacturer=None, Manufacturer="Texas Instruments", Supplier Part Number 1=CSD13306W-ND, Value1=0.01, Value2="8.6 nC"
Q3: library part CMP-0000193-1, "MOSFET, N-CH, 12 V, 22 A, DQK0006C (WSON-6)", Alternate Manufacturer=None, Manufacturer="Texas Instruments", Supplier Part Number 1=CSD13202Q2-ND, Value1=0.009, Value2="5.1 nC"
R1 R2: library part CMP-0020833-2, "RES, 0, 1%, 0.5 W, 0805", Manufacturer=Keystone, Power_W=500mW, Supplier Part Number 1=36-5106CT-ND, TempCo=ppm/C, Tolerance_%=1%, Value2=0.5W, Value_Code=0
R3 R31 R32 R33: library part CMP-0022743-5, "RES, 10.2 k, 1%, 0.1 W, 0603", Manufacturer=Yageo, Power_W=100mW, Supplier Part Number 1=311-10.2KHRCT-ND, TempCo="100 ppm/C", Tolerance_%=1%, Value2=0.1W, Value_Code=10k2, ValueDisplayed=10.2k
R4 R12: library part CMP-0023283-4, "RES, 806 k, 1%, 0.1 W, 0603", Manufacturer=Yageo, Power_W=100mW, Supplier Part Number 1=311-806KHRCT-ND, TempCo="100 ppm/C", Tolerance_%=1%, Value2=0.1W, Value_Code=806k
R5 R8 R13 R17 R21 R22 R23 R24 R27 R29 R30 R34 R35 R36 R39 R40 R45 R46 R47 R48: library part CMP-0023343-3, "RES, 0, 1%, 0.1 W, AEC-Q200 Grade 0, 0603", Manufacturer="Stackpole Electronics Inc", Power_W=100mW, Supplier Part Number 1=RMCF0603ZT0R00CT-ND, TempCo=ppm/C, Tolerance_%=1%, Value2=0.1W, Value_Code=0
R6 R10: library part CMP-0021990-4, "RES, 100 k, 1%, 0.1 W, AEC-Q200 Grade 0, 0603", Manufacturer=Vishay-Dale, Power_W=100mW, Supplier Part Number 1=541-100KHCT-ND, TempCo="100 ppm/C", Tolerance_%=1%, Value2=0.1W, Value_Code=100k
R7 R37: library part CMP-0022899-4, "RES, 1.00 M, 1%, 0.1 W, 0603", Manufacturer=Yageo, Power_W=100mW, Supplier Part Number 1=311-1.00MHRCT-ND, TempCo="100 ppm/C", Tolerance_%=1%, Value2=0.1W, Value_Code=1M00, ValueDisplayed=1.00M
R9: library part CMP-0022880-5, "RES, 1.40 k, 1%, 0.1 W, 0603", Manufacturer=Yageo, Power_W=100mW, Supplier Part Number 1=311-1.40KHRCT-ND, TempCo="100 ppm/C", Tolerance_%=1%, Value2=0.1W, Value_Code=1k40, ValueDisplayed=1.40k
R11: library part CMP-0023068-4, "RES, 390 k, 1%, 0.1 W, 0603", Manufacturer=Yageo, Power_W=100mW, Supplier Part Number 1=311-390KHRCT-ND, TempCo="100 ppm/C", Tolerance_%=1%, Value2=0.1W, Value_Code=390k
R14 R16 R18 R20: library part CMP-0023341-3, "RES, 10.0 k, 1%, 0.1 W, AEC-Q200 Grade 0, 0603", Manufacturer="Stackpole Electronics Inc", Power_W=100mW, Supplier Part Number 1=RMCF0603FT10K0CT-ND, TempCo="100 ppm/C", Tolerance_%=1%, Value2=0.1W, Value_Code=10k0, ValueDisplayed=10.0k
R15 R42: library part CMP-0022680-4, "RES, 1.00 k, 1%, 0.1 W, 0603", Manufacturer=Panasonic, Power_W=100mW, Supplier Part Number 1=P1.00KHCT-ND, TempCo="100 ppm/C", Tolerance_%=1%, Value2=0.1W, Value_Code=1k00, ValueDisplayed=1.00k
R19: library part CMP-0016782-3, "RES, 20.0, 1%, 0.5 W, AEC-Q200 Grade 0, 1206", Manufacturer=Vishay-Dale, Power_W=500mW, Supplier Part Number 1=541-20.0UCT-ND, TempCo="100 ppm/C", Tolerance_%=1%, Value2=0.5W, Value_Code=20R0, ValueDisplayed=20.0
R25: library part CMP-0022311-4, "RES, 2.49, 1%, 0.1 W, AEC-Q200 Grade 0, 0603", Manufacturer=Vishay-Dale, Power_W=100mW, Supplier Part Number 1=541-2.49HHCT-ND, TempCo="100 ppm/C", Tolerance_%=1%, Value2=0.1W, Value_Code=2R49, ValueDisplayed=2.49
R26: library part CMP-0022448-4, "RES, 49.9, 1%, 0.1 W, AEC-Q200 Grade 0, 0603", Manufacturer=Vishay-Dale, Power_W=100mW, Supplier Part Number 1=541-49.9HCT-ND, TempCo="100 ppm/C", Tolerance_%=1%, Value2=0.1W, Value_Code=49R9, ValueDisplayed=49.9
R28: library part CMP-0017252-2, "RES, 0.05, 1%, 0.5 W, 1206", Manufacturer=Bourns, Power_W=500mW, Supplier Part Number 1=1865243, TempCo="150 ppm/C", Tolerance_%=1%, Value2=0.5W, Value_Code=R050, ValueDisplayed=0.05
R38: library part CMP-0023004-4, "RES, 2.00 M, 1%, 0.1 W, 0603", Manufacturer=Yageo, Power_W=100mW, Supplier Part Number 1=311-2.00MHRCT-ND, TempCo="100 ppm/C", Tolerance_%=1%, Value2=0.1W, Value_Code=2M00, ValueDisplayed=2.00M
R41: library part CMP-0022735-5, "RES, 100 k, 1%, 0.1 W, 0603", Manufacturer=Yageo, Power_W=100mW, Supplier Part Number 1=311-100KHRCT-ND, TempCo="100 ppm/C", Tolerance_%=1%, Value2=0.1W, Value_Code=100k
R43: library part CMP-0022692-3, "RES, 22.0 k, 1%, 0.1 W, AEC-Q200 Grade 0, 0603", Manufacturer=Panasonic, Power_W=100mW, Supplier Part Number 1=P22.0KHCT-ND, TempCo="100 ppm/C", Tolerance_%=1%, Value2=0.1W, Value_Code=22k0, ValueDisplayed=22.0k
R44: library part CMP-0023128-4, "RES, 470 k, 1%, 0.1 W, 0603", Manufacturer=Yageo, Power_W=100mW, Supplier Part Number 1=311-470KHRCT-ND, TempCo="100 ppm/C", Tolerance_%=1%, Value2=0.1W, Value_Code=470k
S2: library part CMP-0002113-1, "Switch, Push Button, SMD", CurrentRating_mA=50A, Manufacturer=Alps, Supplier Part Number 1=688-SKRKAE
TP2 TP3 TP5 TP6 VIN: library part CMP-0055137-1, "Test Point, Miniature, Red, TH", Color=Red, Manufacturer=Keystone, Supplier Part Number 1=36-5000-ND
U1: library part CMP-0076712-5, "High Current, High Efficiency Single Inductor Buck-Boost Converter, DLA0010A (VSON-HR-10)", Alternate Manufacturer="Texas Instruments", Alternate PartNumber=TPS63802DLAT, Operating Temperature Range="-40 to 125 C"
U2: library part CMP-0013459-3, "12V eFuse with Over Voltage Protection, DSG0008A (WSON-8)", Alternate Manufacturer="Texas Instruments", Alternate PartNumber=TPS259571DSGT
U3 U8: library part CMP-0040903-1, "17 uA, MicroPower, Precision, Zero Drift CMOS Operational Amplifier, 1.8 to 5.5 V, -40 to 125 degC, 5-pin SOT23 (DBV5), Green (RoHS & no Sb/Br)", Manufacturer="Texas Instruments", Total Supply Voltage(Max)(+5V is 5, +/-5V is 10)=5.5, Total Supply Voltage(Min)(+5V is 5, +/-5V is 10)=1.8
U4 U5: library part CMP-0041001-1, "50 MHz, Low-Noise, Single-Supply Rail-to-Rail Operational Amplifier, 2.2 to 5.5 V, -40 to 125 degC, 5-pin SOT23 (DBV5), Green (RoHS & no Sb/Br)", Manufacturer="Texas Instruments", Total Supply Voltage(Max)(+5V is 5, +/-5V is 10)=5.5, Total Supply Voltage(Min)(+5V is 5, +/-5V is 10)=2.2
U6: library part CMP-0074345-3, "10-Ohm SPDT Analog Switch, DCK0006A (SOT-SC70-6)", Alternate Manufacturer="Texas Instruments", Alternate PartNumber=TS5A9411DCKT, Operating Temperature Range="-40 to 85 C", Rating=Catalog
U7: library part CMP-0085889-1, "Small-Size Micropower Low-Voltage Comparator, DCK0005A (SOT-SC70-5)", Alternate Manufacturer="Texas Instruments", Alternate PartNumber=TLV7021DCKT, Operating Temperature Range="-40 to 125 C", Rating=Catalog
ZZ1: library part AssemblyNoteLabel, Alternate Manufacturer=-
ZZ2 ZZ3 ZZ4: library part AssemblyNote, Alternate Manufacturer=-

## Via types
v1: diameter 24, hole 12, Top Layer to Bottom Layer, tented both sides, 114 vias
v2: diameter 24, hole 12, Top Layer to Bottom Layer, 4 vias
v3: diameter 19.68, hole 7.87, Top Layer to Bottom Layer, 2 vias

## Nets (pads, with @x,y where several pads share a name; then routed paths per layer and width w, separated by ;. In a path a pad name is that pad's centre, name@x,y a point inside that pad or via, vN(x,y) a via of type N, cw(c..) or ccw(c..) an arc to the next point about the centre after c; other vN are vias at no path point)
3V3: J2.1 J5.4 | length 474.1
  Top Layer w20: v1(402,1503) 402,1494 424.94,1471.06 J5.4@471,1471.06
  Bottom Layer w20: J2.1@250,1227.95 289,1266.95 289,1473 319,1503 v1(402,1503)
FET_SAT: J3.2 R32.1 R44.2 U7.1 | length 629.4
  Top Layer w15: v1(1723,912.71) 1724.5,914.22 R32.1@1769,914.22 1830,914.22 R44.2@1830.59,914.81 ; U7.1@1830.59,812.07 R44.2@1830.59,914.81 ; R44.2@1831,915.22 R44.2@1830.59,914.81
  Bottom Layer w15: v1(1723,912.71) 1938.24,1127.95 J3.2@2050,1127.95 J3.2@2050,1129.37
GND: C6.2 C7.2 C8.2 C9.2 C10.2 C11.2 C12.2 C13.2 C14.2 C15.2 C16.2 C17.2 C18.2 C19.2 C20.2 C21.2 C22.2 C23.2 C24.2 C26.2 C27.2 C28.2 D6.2 J1.5 J3.1 J4.2 J5.1 Q3.4 Q3.7 R9.1 R10.2 R11.1 R20.1 R26.1 R33.1 R36.1 R37.1 R41.1 R45.2 S2.2 U1.3 U2.8 U2.9@680.32,1186.37 U3.2 U4.2 U5.2 U6.3 U7.2 U8.2 | length 3108.1
  Top Layer w8: C7.2@352.5,996 352.5,1031.5 353,1032 v1(353,1033)
  Top Layer w9.84: U1.3@652.35,621.95 v1(770,622) v1(770,622)
  Top Layer w10: v1(861,606) 861,569.2 Q3.4@896.61,533.59 Q3.7@931.26,533.59
  Top Layer w15: v1(93,1058) 94,1057 S2.2@94,1013.68 ; v1(1149.44,869) 1150.5,867.95 R36.1@1150.5,828.21 ; v1(1177,492) 1177,490 1193.63,473.37 C10.2@1233.43,473.37 ; U6.3@1181.85,681.85 1229.57,681.85 C16.2@1240.56,692.83 1318.17,692.83 C15.2@1322,689 v1(1382,689) ; U4.2@1200.87,299.68 1247.68,299.68 1261.18,313.18 C11.2@1261.18,399.37 1261.18,445.61 C10.2@1233.43,473.37 ; v1(1234,527) 1233.57,527.43 1233.43,527.43 C10.2@1233.43,473.37 ; C17.2@1239.5,833.53 v1(1239.5,881.5) v1@1240,882 ; U5.2@1373.71,842.62 1532.76,842.62 C14.2@1537,838.38 1569.62,838.38 C13.2@1604,804 ; v1(1604,752) C13.2@1604,804 ; v1(1655,804) C13.2@1604,804 ; U7.2@1805,812.07 1805,784.71 1816,773.71 1879.38,773.71 C21.2@1883,777.34 1933.33,777.34 C20.2@1950,794 ; C8.2@1893,1414.22 v1(1893,1475) ; v1(1899.29,70) R37.1@1899.29,128.5 ; v1(1924,848) 1924,820 C20.2@1950,794 ; v1(1974,849) 1974,818 C20.2@1950,794
  Top Layer w20: v1(110.94,1352.94) J5.1@171,1352.94 ; R26.1@965.5,357 1016,357 v1(1040,381) ; C22.2@1086.84,485.7 1129.7,485.7 v1(1130,486) ; v1(1613,1334) R20.1@1613,1379.5 ; v1(1646,673) 1653.5,680.5 C23.2@1653.5,727.71 ; U8.2@1722.6,1447.22 1722.6,1411.4 1745.16,1388.84 C9.2@1824,1388.84 1867.62,1388.84 C8.2@1893,1414.22 v1(1953.78,1414.22) v1@1955,1413 ; v1(1767.29,476) C27.2@1813.29,476 ; U3.2@1782.15,296 1816.6,296 1846.29,325.69 C28.2@1846.29,404 1813.29,437 C27.2@1813.29,476 ; v1(1813.29,533) C27.2@1813.29,476 ; v1@1847,1283 v1(1847.5,1282.5) R41.1@1847.5,1240.22 C12.2@1847.5,1177.22 ; C26.2@1853.78,584 1869.78,568 1884.78,583 v1(1901,583) ; D6.2@2110.81,234 2110.81,196.47 v1(2111.29,196)
  Bottom Layer w15: v1(336,1450) 380,1450 C18.2@382,1448 382,1392.38 C19.2@396.38,1378 ; v1(1149.44,869) 1150.5,867.95 C24.2@1150.5,828.21
  Bottom Layer w20: v1(1646,673) 1646,720.21 R33.1@1653.5,727.71
  other v1: 179,74 220,74 180,113 221,113 179,154 220,154 265,154 811,621 512.32,1126.37 512.32,1167.37 512.32,1208.37 512.32,1249.37 512.32,1290.37
  other v3: 658.67,1186.37 701.97,1186.37
GNDP: C1.2 C2.2 C3.2 C4.2 C5.2 C25.2 GND.1 R8.1 R28.1 R45.1 U1.8 | length 423
  Top Layer w8: U1.8@595.27,621.95 U1.8@616.92,621.95
  Top Layer w9.84: 533.95,621.95 U1.8@595.27,621.95
  Top Layer w20: v1(748,501) 796.5,549.5 R8.1@796.5,576 ; C5.2@784.5,1063 v1(828,1063) ; C4.2@792.5,1274 794.5,1272 v1(838,1272) ; v1(806.41,953) R28.1@849.91,953 ; R28.1@849.91,949 860,938.91 v1(860,895) ; v1(853,1006) 853,953.91 R28.1@853.91,953
  other v1: 329,55 371,55 371,100 326,146 371,146
I_SENSE: J3.9 Q2.B2 Q2.C2 R28.2 U5.4 | length 1833
  Top Layer w10: 1108,979 1132.25,1003.25 ; Q2.B2@1227,1011 Q2.B2@1226.08,1010.08 ; 1228,993 1228,1008.16 Q2.B2@1226.08,1010.08 ; 1132.25,1003.25 1225.27,1003.25 1225.27,1009.27 Q2.B2@1226.08,1010.08 ; 1132.25,1003.25 1139.16,1010.16 Q2.C2@1206.32,1010.16 Q2.B2@1226,1010.16 Q2.B2@1226.08,1010.08
  Top Layer w15: R28.2@966.09,951 966.09,956.09 989,979 1108,979 ; v1@1025,951 v1(1026,952)
  Top Layer w20: v1@1481.98,763.02 U5.4@1481.98,805.22
  PWR w15: v1(1073,912) 1073,829 1139,763 v1(1482,763) 1482,496 1550.05,427.95 J3.9@2050,427.95
  other v1: 1028,911 1072,952
LED_DRV_SUP: J1.1 R27.1
LED_X: D6.1 J3.10 | length 95.8
  Top Layer w15: J3.10@2047.29,327.95 2047.29,238.47 D6.1@2051.76,234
